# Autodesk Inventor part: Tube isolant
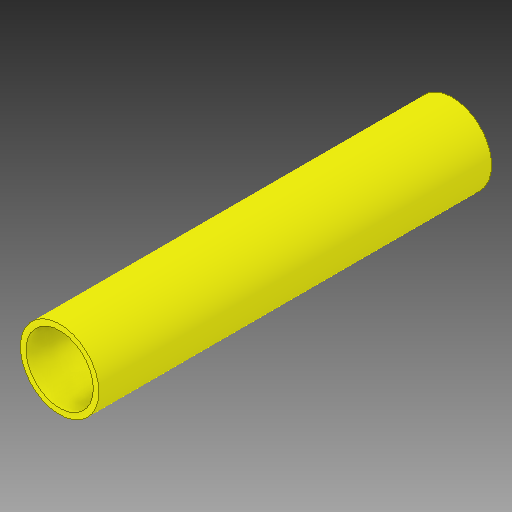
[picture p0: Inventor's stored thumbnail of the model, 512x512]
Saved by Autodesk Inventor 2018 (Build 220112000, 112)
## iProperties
Created: 2009-05
Part Number: Tube isolant
Material: Générique
Document SubType Name: Modeling
Designer: TJ
Density: 1 g/cm^3
Appearance: Par défaut
Author: TJ
Sending System: SolidWorks 2008
Last Author: Roger
Last Saved: 2011-02-17
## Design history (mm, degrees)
extrude "Extrusion1"
node "Solide1"
